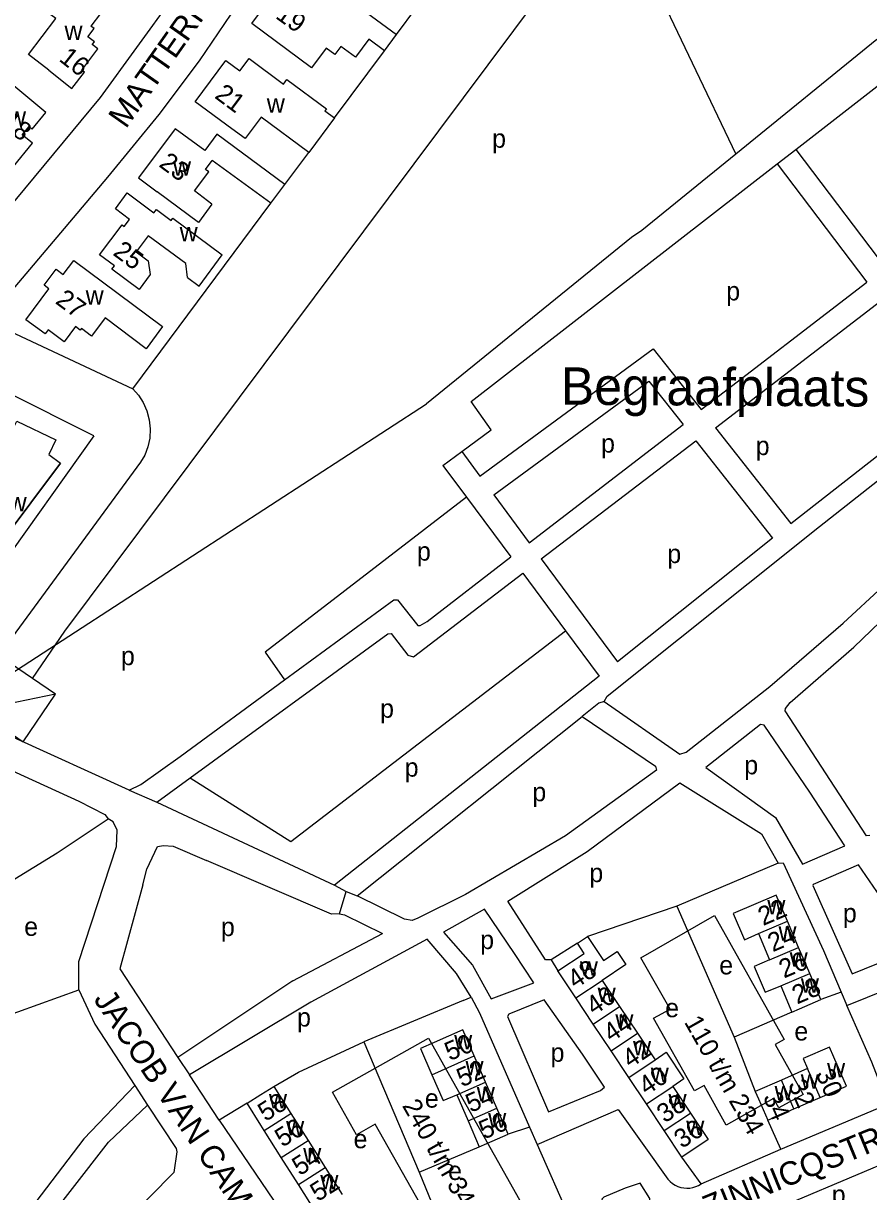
# Model space of a CAD drawing. Extents: x 158848 to 160613, y 385889 to 387762.
# Drawn here: x 159449.2 to 159630.1, y 386409.7 to 386659.8 of the extents above; entities that cross this region are included whole.
import ezdxf

# ---------------------------------------------------------------- set-up
doc = ezdxf.new("R2010")
doc.units = 0
for name, color, linetype in [('BLT_Basislijn', 7, 'Continuous'), ('BLT_Bebouwing', 7, 'Continuous'), ('BLT_Centroide', 7, 'Continuous'), ('BLT_Hoogspanningsmast_en_leidingen', 7, 'Continuous'), ('BLT_Huisnummer', 7, 'Continuous'), ('BLT_Huisnummer_ tussenligend', 7, 'Continuous'), ('BLT_Huisnummer_zonder_bebouwing', 7, 'Continuous'), ('BLT_Onderverdeling_panden', 7, 'Continuous'), ('BLT_Plantopo', 7, 'Continuous'), ('BLT_Straatnaam', 7, 'Continuous'), ('BLT_Terrein_beschrifting', 7, 'Continuous')]:
    doc.layers.add(name, color=color, linetype=linetype)

msp = doc.modelspace()

# ---------------------------------------------------------------- linework, layer by layer
at = {"layer": 'BLT_Basislijn'}
for p, q in [((159465.7, 386643.87), (159484.43, 386669.82)), ((159529, 386657.37), (159533.39, 386663.27)), ((159515.73, 386639.55), (159526.45, 386653.92)), ((159442.93, 386616.47), (159465.7, 386643.87)), ((159614.48, 386632.78), (159652.08, 386583.03)), ((159505.12, 386625.27), (159510.29, 386632.12)), ((159610.53, 386629.71), (159629.72, 386604.33)), ((159472.6, 386581.49), (159502.14, 386621.26)), ((159594.22, 386577.08), (159629.72, 386604.33)), ((159597.32, 386573.15), (159632.73, 386600.34)), ((159546.9, 386562.84), (159584, 386590.07)), ((159584, 386590.07), (159594.22, 386577.08)), ((159619.58, 386552.04), (159662.24, 386585.81)), ((159549.87, 386558.82), (159583.06, 386583.18)), ((159583.06, 386583.18), (159590.38, 386573.88)), ((159613.45, 386552.66), (159648.15, 386579.94)), ((159436.03, 386513.78), (159535.46, 386578.29)), ((159557.46, 386548.57), (159590.38, 386573.88)), ((159597.32, 386573.15), (159613.45, 386552.66)), ((159464.23, 386571.47), (159427.12, 386519.34)), ((159560.03, 386545.1), (159593.12, 386570.4)), ((159593.12, 386570.4), (159609.52, 386549.57)), ((159538.97, 386565.14), (159542.99, 386568.12)), ((159542.99, 386568.12), (159546.9, 386562.84)), ((159474.24, 386565.81), (159436.03, 386513.78)), ((159538.97, 386565.14), (159544.03, 386558.31)), ((159544.03, 386558.31), (159553.5, 386545.53)), ((159549.87, 386558.82), (159557.46, 386548.57)), ((159609.52, 386549.57), (159576.31, 386523.11)), ((159560.03, 386545.1), (159576.31, 386523.11)), ((159556.06, 386542.06), (159565.22, 386529.68)), ((159565.22, 386529.68), (159572.38, 386520.01)), ((159572.38, 386520.01), (159515.76, 386475.24)), ((159482.71, 386502.79), (159505.08, 386519.19)), ((159520.58, 386472.97), (159568.76, 386511.35)), ((159471.83, 386495.63), (159447.04, 386506.91)), ((159477.73, 386493.01), (159484.86, 386498.21)), ((159471.83, 386495.63), (159477.73, 386493.01)), ((159625.02, 386483.67), (159617.53, 386495.16)), ((159477.73, 386493.01), (159515.76, 386475.24)), ((159615.93, 386479.73), (159625.02, 386483.67)), ((159610.71, 386479.97), (159589.04, 386470.76)), ((159474.75, 386475.32), (159473.09, 386469.33)), ((159515.76, 386475.24), (159518.29, 386473.93)), ((159516.82, 386469.1), (159518.29, 386473.93)), ((159518.29, 386473.93), (159520.58, 386472.97)), ((159547.84, 386470.12), (159539.07, 386465.22)), ((159554.29, 386460.65), (159547.84, 386470.12)), ((159589.04, 386470.76), (159569.94, 386464.28)), ((159589.04, 386470.76), (159601.29, 386442.71)), ((159506.82, 386454.77), (159526.04, 386464.89)), ((159567.76, 386462.83), (159562.17, 386459.27)), ((159558.4, 386454.38), (159554.29, 386460.65)), ((159562.17, 386459.27), (159563.57, 386456.9)), ((159438.38, 386444.67), (159461.05, 386452.86)), ((159506.82, 386454.77), (159482.2, 386438.36)), ((159549.31, 386450.96), (159558.4, 386454.38)), ((159624.19, 386452.34), (159619.88, 386450.76)), ((159624.19, 386452.34), (159625.41, 386449.52)), ((159543.27, 386450.59), (159522.02, 386441.74)), ((159543.27, 386450.59), (159544.99, 386451.28)), ((159613.67, 386448.1), (159601.29, 386442.71)), ((159601.29, 386442.71), (159605.79, 386431.11)), ((159522.02, 386441.74), (159533.91, 386413.81)), ((159482.2, 386438.36), (159484.72, 386434.63)), ((159473, 386432.36), (159475.74, 386428.18)), ((159491.08, 386424.94), (159484.72, 386434.63)), ((159497.05, 386428.56), (159491.08, 386424.94)), ((159491.08, 386424.94), (159518.29, 386385)), ((159611.3, 386418.76), (159608.49, 386424.92)), ((159557.53, 386423.46), (159552.96, 386421.93)), ((159557.53, 386423.46), (159559.12, 386419.76)), ((159533.91, 386413.81), (159546.76, 386419.24)), ((159559.12, 386419.76), (159566.17, 386403.78)), ((159594.26, 386411.31), (159611.3, 386418.76)), ((159594.26, 386411.31), (159590.12, 386417.03)), ((159533.91, 386413.81), (159538.67, 386402.16))]:
    msp.add_line(p, q, dxfattribs=at)
for points in [[(159640.46, 386758.72), (159582.99, 386670.93), (159601.65, 386631.78)], [(159525.43, 386728.39), (159522.28, 386725.59), (159524.59, 386715.96), (159523.16, 386709.25), (159518.85, 386700.63), (159512.15, 386689.13), (159503.53, 386676.68), (159494.92, 386663.75), (159486.78, 386651.78), (159478.17, 386640.28), (159467.16, 386626.87), (159457.11, 386614.9), (159446.58, 386602.45), (159442.27, 386597.18), (159445.23, 386594.38), (159472.6, 386581.49)], [(159631.81, 386656.29), (159601.65, 386631.78)], [(159614.48, 386632.78), (159645.31, 386656.72), (159664.62, 386630.27), (159663.76, 386629.25), (159669.81, 386618.52), (159668.03, 386615.51), (159677.14, 386603.26), (159659.74, 386589.06)], [(159464.23, 386571.47), (159427.07, 386590.06), (159421.88, 386590.64), (159403.73, 386596.98), (159386.43, 386603.9), (159368.85, 386611.97), (159352.13, 386620.33), (159334.84, 386629.26), (159323.02, 386636.18), (159319.56, 386638.2), (159318.41, 386637.62), (159293.33, 386585.16), (159293.91, 386582.57), (159426.49, 386519.73), (159427.12, 386519.34)], [(159610.53, 386629.71), (159614.48, 386632.78)], [(159601.65, 386631.78), (159581.52, 386615.43), (159579.3, 386613.91), (159535.46, 386578.29)], [(159542.99, 386568.12), (159549.3, 386572.73), (159545.03, 386578.83), (159610.53, 386629.71)], [(159573.48, 386514.55), (159589.7, 386503.28), (159591.03, 386503.75), (159608.94, 386517.82), (159624.63, 386531.34), (159650.13, 386554.93), (159661.12, 386566.05), (159675.68, 386579.96), (159696.76, 386599.11), (159720.05, 386617.5)], [(159472.6, 386581.49), (159473.79, 386580.15), (159474.81, 386578.58), (159475.61, 386576.82), (159476.12, 386574.92), (159476.33, 386572.95), (159476.22, 386570.99), (159475.82, 386569.1), (159475.14, 386567.35), (159474.24, 386565.81)], [(159544.03, 386558.31), (159500.93, 386525.17), (159505.08, 386519.19)], [(159573.48, 386514.55), (159574.14, 386515.74), (159619.58, 386552.04)], [(159630.33, 386485.91), (159629.62, 386485.81), (159612.22, 386512.57), (159612.29, 386513.11), (159613.3, 386514.39), (159626.94, 386526.22), (159649.36, 386547.83), (159649.99, 386548.11), (159652.21, 386545.34), (159677.32, 386509.58)], [(159505.08, 386519.19), (159528.45, 386536.33), (159529.24, 386536.37), (159533.63, 386530.87), (159534.09, 386530.87), (159535.57, 386531.74), (159553.5, 386545.53)], [(159484.86, 386498.21), (159527.18, 386529.09), (159527.91, 386529.12), (159531.47, 386524.5), (159532.68, 386524.18), (159556.06, 386542.06)], [(159484.86, 386498.21), (159506.42, 386484.59), (159565.22, 386529.68)], [(159573.48, 386514.55), (159572.33, 386514.26), (159568.76, 386511.35)], [(159568.76, 386511.35), (159584.45, 386500.74), (159584.7, 386499.85), (159565.2, 386485.85), (159543.82, 386473.3), (159533.61, 386468.19), (159532.36, 386467.68), (159530.71, 386467.98), (159520.58, 386472.97)], [(159617.53, 386495.16), (159607.72, 386509.55), (159606.97, 386509.68), (159595.26, 386500.44), (159610.15, 386489.76), (159615.93, 386479.73)], [(159437.6, 386503.98), (159461.06, 386493.23), (159466.62, 386490.42), (159467.3, 386489.43)], [(159471.83, 386495.63), (159474.32, 386496.78), (159482.71, 386502.79)], [(159562.17, 386459.27), (159560.9, 386459.28), (159552.88, 386471.85), (159569.82, 386482.49), (159589.7, 386497.14), (159607.12, 386486.22), (159610.71, 386479.97)], [(159428.22, 386464.88), (159456.38, 386482.21), (159467.3, 386489.43)], [(159461.05, 386452.86), (159461.06, 386458.9), (159469.11, 386483.55), (159469.23, 386487.03), (159468.38, 386488.81), (159467.3, 386489.43)], [(159474.75, 386475.32), (159475.61, 386478.66), (159477.88, 386483.56), (159479.18, 386483.78), (159481.26, 386483.62), (159488.35, 386480.55)], [(159516.82, 386469.1), (159515.09, 386469.02), (159488.35, 386480.55)], [(159610.71, 386479.97), (159611.81, 386480.08), (159620.45, 386461.27), (159624.19, 386452.34)], [(159635.8, 386468.19), (159627.94, 386479.64), (159618.23, 386475.44), (159618.12, 386475.16), (159626.54, 386456.26), (159634.84, 386459.65), (159639.77, 386462.04), (159635.8, 386468.19)], [(159473.09, 386469.33), (159469.81, 386457.37), (159482.2, 386438.36)], [(159516.82, 386469.1), (159517.89, 386468.94), (159526.04, 386464.89)], [(159539.07, 386465.22), (159545.31, 386458.17), (159549.31, 386450.96)], [(159535.58, 386463.67), (159510.69, 386450.21), (159484.72, 386434.63)], [(159544.99, 386451.28), (159541.85, 386456.33), (159535.58, 386463.67)], [(159625.41, 386449.52), (159643.13, 386456.61), (159654.63, 386440.39), (159655.51, 386439.74), (159657.46, 386439.11), (159660.35, 386439.44), (159661.15, 386439.82)], [(159461.05, 386452.86), (159464.46, 386445.5), (159473, 386432.36)], [(159544.99, 386451.28), (159546.77, 386447.9), (159557.53, 386423.46)], [(159568.83, 386439.08), (159560.65, 386450.74), (159553.04, 386447.67), (159552.76, 386447.14), (159561.58, 386426.72), (159572.67, 386431.28), (159573.56, 386432.01), (159568.83, 386439.08)], [(159611.3, 386418.76), (159631.95, 386427.42), (159633.52, 386428.63), (159633.71, 386429.77), (159630.8, 386437.39), (159625.41, 386449.52)], [(159502.76, 386432.18), (159508.02, 386435.26), (159522.02, 386441.74)], [(159473, 386432.36), (159462.11, 386420.94), (159440.16, 386392.21), (159414.81, 386370.75), (159413.46, 386368.41), (159413.43, 386365.42), (159415.73, 386361.26), (159495.3, 386232.05)], [(159450.18, 386340.58), (159439.6, 386334.13), (159437.93, 386333.69), (159418.04, 386365.52), (159418.17, 386367.3), (159419.09, 386369.02), (159444.29, 386390.46), (159467.36, 386420.26), (159475.74, 386428.18)], [(159475.74, 386428.18), (159481.84, 386418.87), (159481.99, 386418.14), (159481.36, 386413.78), (159439.89, 386371.77), (159438.58, 386370.38), (159436.98, 386366.85), (159437.23, 386361.6), (159450.18, 386340.58)], [(159559.12, 386419.76), (159576.5, 386427.2), (159587.14, 386412.3)], [(159614.47, 386407.77), (159637.5, 386417.49), (159638.83, 386417.79), (159642.29, 386409.95)], [(159577.99, 386410.41), (159573.39, 386408.49), (159572.99, 386408.05), (159573.95, 386405.27), (159575.54, 386403.54), (159576.65, 386403.09), (159578.72, 386403.31), (159582.57, 386405.43), (159583.17, 386406.08), (159583.27, 386408.15), (159581.15, 386411.45), (159577.99, 386410.41)], [(159587.14, 386412.3), (159587.59, 386411.82), (159588.1, 386411.41), (159588.65, 386411.06), (159589.25, 386410.78), (159589.87, 386410.57), (159590.51, 386410.44), (159591.16, 386410.39), (159591.82, 386410.42), (159592.46, 386410.53), (159593.09, 386410.72), (159593.69, 386410.98), (159594.26, 386411.31)]]:
    msp.add_lwpolyline(points, dxfattribs=at)
at = {"layer": 'BLT_Bebouwing'}
for p, q in [((159615.09, 386461.95), (159612.7, 386467.54)), ((159606.49, 386464.89), (159608.88, 386459.29)), ((159567.76, 386462.83), (159569.94, 386464.28)), ((159617.48, 386456.35), (159615.09, 386461.95)), ((159567.42, 386451.12), (159563.57, 386456.9)), ((159573.06, 386454.87), (159576.79, 386449.26)), ((159619.88, 386450.76), (159617.48, 386456.35)), ((159611.28, 386453.7), (159613.67, 386448.1)), ((159571.16, 386445.51), (159567.42, 386451.12)), ((159576.79, 386449.26), (159580.58, 386443.56)), ((159574.95, 386439.81), (159571.16, 386445.51)), ((159580.58, 386443.56), (159584.38, 386437.87)), ((159548.11, 386433.11), (159545.68, 386438.69)), ((159578.74, 386434.12), (159574.95, 386439.81)), ((159616.98, 386435.98), (159611.41, 386433.55)), ((159550.54, 386427.52), (159548.11, 386433.11)), ((159582.54, 386428.42), (159578.74, 386434.12)), ((159611.41, 386433.55), (159605.79, 386431.11)), ((159502.76, 386432.18), (159506.43, 386426.39)), ((159541.91, 386430.41), (159544.34, 386424.83)), ((159588.17, 386432.17), (159591.96, 386426.47)), ((159614.11, 386427.37), (159619.72, 386429.82)), ((159552.96, 386421.93), (159550.54, 386427.52)), ((159586.33, 386422.72), (159582.54, 386428.42)), ((159608.49, 386424.92), (159614.11, 386427.37)), ((159506.43, 386426.39), (159510.09, 386420.6)), ((159544.34, 386424.83), (159546.76, 386419.24)), ((159504.38, 386416.98), (159500.71, 386422.77)), ((159590.12, 386417.03), (159586.33, 386422.72)), ((159510.09, 386420.6), (159513.75, 386414.8)), ((159508.04, 386411.19), (159504.38, 386416.98)), ((159513.75, 386414.8), (159517.42, 386409.01)), ((159511.71, 386405.4), (159508.04, 386411.19))]:
    msp.add_line(p, q, dxfattribs=at)
for points in [[(159498.05, 386659.71), (159504.39, 386668.27), (159506.05, 386667.02), (159508.68, 386670.57), (159514.67, 386666.12), (159514.4, 386665.77), (159516.11, 386664.52), (159517.29, 386666.08), (159529, 386657.37)], [(159454.6, 386649.75), (159450.25, 386653.07), (159456.15, 386660.78), (159455.07, 386661.61), (159460.16, 386668.27)], [(159460.16, 386668.27), (159465.69, 386661.9), (159463.63, 386659.18)], [(159454.6, 386649.75), (159459.54, 386645.8), (159462.23, 386649.31), (159461.67, 386649.74), (159465.14, 386654.29), (159463.92, 386655.22), (159464.39, 386655.84), (159462.99, 386656.91), (159464.32, 386658.65), (159463.63, 386659.18)], [(159526.45, 386653.92), (159523.11, 386656.41), (159520.23, 386652.54), (159517.14, 386654.85), (159515.83, 386653.09), (159513.99, 386654.46), (159510.84, 386650.23), (159498.05, 386659.71)], [(159526.45, 386653.92), (159529, 386657.37)], [(159510.29, 386632.12), (159500.07, 386639.68), (159496.61, 386635.11), (159493.81, 386637.18), (159485.96, 386642.99), (159492.5, 386651.81), (159495.49, 386649.61), (159497.48, 386652.25), (159504.84, 386646.77), (159505.57, 386647.75), (159514.04, 386641.48)], [(159437.77, 386635.89), (159445.06, 386629.88), (159445.49, 386630.39), (159447.02, 386629.13), (159451.13, 386634.13), (159448.94, 386635.92), (159450.43, 386637.7), (159451.08, 386637.15), (159453.99, 386640.72), (159446.7, 386646.73)], [(159514.04, 386641.48), (159513.71, 386641.05), (159515.73, 386639.55)], [(159515.73, 386639.55), (159510.29, 386632.12)], [(159505.12, 386625.27), (159490.58, 386636.07), (159487.98, 386632.52), (159481.63, 386637.18), (159473.82, 386626.72), (159477.82, 386623.73)], [(159489.51, 386621.07), (159485.78, 386623.9), (159488.85, 386627.97), (159488.15, 386628.5), (159489.61, 386630.43)], [(159502.14, 386621.26), (159489.61, 386630.43)], [(159502.14, 386621.26), (159505.12, 386625.27)], [(159468.12, 386607.12), (159468.66, 386607.83), (159465.49, 386610.18), (159470.29, 386616.62), (159470.76, 386616.27), (159471.9, 386617.8), (159468.86, 386620.06), (159471.39, 386623.46)], [(159471.39, 386623.46), (159477.12, 386619.19)], [(159489.51, 386621.07), (159486.63, 386617.14), (159477.82, 386623.73)], [(159477.12, 386619.19), (159477.65, 386619.9), (159480.81, 386617.56), (159481.17, 386618.04), (159491.73, 386610.18)], [(159484.32, 386605.36), (159483.92, 386608.34), (159475.88, 386614.29), (159473.32, 386610.83), (159475.87, 386608.95), (159476.29, 386605.97), (159473.94, 386602.79), (159468.12, 386607.12)], [(159486.77, 386603.54), (159491.73, 386610.18)], [(159478.98, 386594.86), (159475.48, 386590.11), (159466.64, 386596.69), (159463.76, 386592.81), (159461.6, 386594.46), (159461.32, 386594.08), (159460.31, 386594.85), (159457.9, 386591.61), (159454.48, 386594.15), (159453.8, 386593.27), (159449.72, 386596.32), (159454.61, 386602.92), (159453.59, 386603.69), (159456.19, 386607.17), (159457.72, 386605.97), (159459.98, 386608.99), (159478.98, 386594.86)], [(159484.32, 386605.36), (159486.77, 386603.54)], [(159437.43, 386572.83), (159439.55, 386577.36), (159444.27, 386575.15), (159443.81, 386574.18), (159446.87, 386572.72), (159447.77, 386574.61), (159456.14, 386570.62), (159454.62, 386567.44), (159457.08, 386565.63), (159444.41, 386548.63), (159437.96, 386551.73)], [(159444.41, 386548.63), (159457.08, 386565.63)], [(159612.7, 386467.54), (159610.3, 386473.13), (159601.09, 386469.19), (159603.51, 386463.53), (159606.49, 386464.89)], [(159563.57, 386456.9), (159569.21, 386460.66), (159567.76, 386462.83)], [(159569.94, 386464.28), (159573.36, 386459.14), (159576.26, 386461.07), (159578.13, 386458.25), (159573.06, 386454.87)], [(159608.88, 386459.29), (159605.55, 386457.86), (159607.91, 386452.34), (159611.28, 386453.7)], [(159613.67, 386448.1), (159615.28, 386448.79), (159619.88, 386450.76)], [(159545.68, 386438.69), (159543.26, 386444.28), (159537.06, 386441.59), (159534.16, 386440.33), (159536.61, 386434.67)], [(159619.72, 386429.82), (159625.34, 386432.26), (159622.64, 386438.45), (159621.71, 386440.6), (159616.05, 386438.13), (159616.98, 386435.98)], [(159584.38, 386437.87), (159586.77, 386439.49), (159590.54, 386433.83), (159588.17, 386432.17)], [(159536.61, 386434.67), (159539.01, 386429.15), (159541.91, 386430.41)], [(159497.05, 386428.56), (159500, 386430.43), (159502.76, 386432.18)], [(159605.79, 386431.11), (159606.49, 386429.5), (159608.49, 386424.92)], [(159500.71, 386422.77), (159500, 386423.9), (159497.05, 386428.56)], [(159591.96, 386426.47), (159595.75, 386420.78), (159590.12, 386417.03)], [(159546.76, 386419.24), (159548.38, 386419.94), (159552.96, 386421.93)]]:
    msp.add_lwpolyline(points, dxfattribs=at)
at = {"layer": 'BLT_Hoogspanningsmast_en_leidingen'}
for p, q in [((159458.04, 386529.66), (159564.87, 386672.58)), ((159451.11, 386519.48), (159458.04, 386529.66)), ((159456.05, 386516.12), (159439.25, 386512.66))]:
    msp.add_line(p, q, dxfattribs=at)
msp.add_lwpolyline([(159446.18, 386522.84), (159439.25, 386512.66), (159449.12, 386505.94), (159456.05, 386516.12)], close=True, dxfattribs=at)
at = {"layer": 'BLT_Onderverdeling_panden'}
for p, q in [((159606.49, 386464.89), (159612.7, 386467.54)), ((159608.88, 386459.29), (159615.09, 386461.95)), ((159567.42, 386451.12), (159573.06, 386454.87)), ((159611.28, 386453.7), (159617.48, 386456.35)), ((159571.16, 386445.51), (159576.79, 386449.26)), ((159574.95, 386439.81), (159580.58, 386443.56)), ((159536.61, 386434.67), (159545.68, 386438.69)), ((159578.74, 386434.12), (159584.38, 386437.87)), ((159619.72, 386429.82), (159616.98, 386435.98)), ((159541.91, 386430.41), (159548.11, 386433.11)), ((159614.11, 386427.37), (159611.41, 386433.55)), ((159582.54, 386428.42), (159588.17, 386432.17)), ((159544.34, 386424.83), (159550.54, 386427.52)), ((159500.71, 386422.77), (159506.43, 386426.39)), ((159586.33, 386422.72), (159591.96, 386426.47)), ((159504.38, 386416.98), (159510.09, 386420.6)), ((159508.04, 386411.19), (159513.75, 386414.8))]:
    msp.add_line(p, q, dxfattribs=at)
at = {"layer": 'BLT_Plantopo'}
for points in [[(159581.36, 386459.69), (159597.07, 386468.78), (159612.01, 386442.22), (159610.06, 386441.12), (159616.06, 386430.45), (159610.86, 386427.57), (159609.72, 386429.6), (159599.61, 386423.91), (159594.86, 386432.36), (159592.81, 386431.21), (159584.07, 386446.76), (159587.6, 386448.75)], [(159515.35, 386430.93), (159535.89, 386442.48), (159557.28, 386404.45), (159540.77, 386395.17), (159524.5, 386424.1), (159520.46, 386421.83)]]:
    msp.add_lwpolyline(points, close=True, dxfattribs=at)

# ---------------------------------------------------------------- texts
at = {"layer": 'BLT_Centroide'}
for s, p in [('w', (159457.97, 386656.23)), ('w', (159501.27, 386640.62)), ('w', (159445.88, 386637.89)), ('p', (159549.5, 386633.13)), ('w', (159481.2, 386627.16)), ('w', (159482.62, 386613.12)), ('w', (159462.5, 386599.56)), ('p', (159599.6, 386600.46)), ('p', (159572.81, 386567.87)), ('p', (159605.91, 386567.34)), ('w', (159446.02, 386555.28)), ('p', (159533.4, 386544.74)), ('p', (159586.99, 386544.22)), ('p', (159470.05, 386522.36)), ('p', (159525.52, 386511.1)), ('p', (159530.78, 386498.49)), ('p', (159603.47, 386498.99)), ('p', (159558.1, 386493.23)), ('p', (159570.3, 386475.91)), ('w', (159608.4, 386469)), ('p', (159624.57, 386467.31)), ('e', (159449.34, 386464.41)), ('p', (159491.45, 386464.36)), ('w', (159610.79, 386463.41)), ('p', (159546.94, 386461.58)), ('w', (159613.19, 386457.81)), ('w', (159568.28, 386455.92)), ('e', (159598.11, 386456.16)), ('w', (159615.58, 386452.22)), ('w', (159572.08, 386450.23)), ('e', (159586.53, 386446.99)), ('p', (159507.74, 386444.99)), ('w', (159575.88, 386444.55)), ('e', (159614.19, 386442.01)), ('w', (159541.37, 386440.12)), ('p', (159562.01, 386437.45)), ('w', (159579.66, 386438.83)), ('w', (159543.8, 386434.56)), ('w', (159583.45, 386433.14)), ('w', (159621.19, 386434.12)), ('w', (159615.56, 386431.69)), ('w', (159501.73, 386427.47)), ('e', (159535.1, 386427.63)), ('w', (159546.22, 386428.97)), ('w', (159587.25, 386427.45)), ('w', (159609.95, 386429.23)), ('w', (159548.65, 386423.38)), ('w', (159591.05, 386421.75)), ('w', (159505.41, 386421.69)), ('e', (159519.84, 386418.94)), ('w', (159509.06, 386415.89)), ('e', (159540.07, 386412.14)), ('w', (159512.73, 386410.11)), ('p', (159622.19, 386407.03))]:
    msp.add_text(s, height=4, dxfattribs=at).set_placement(p)
at = {"layer": 'BLT_Huisnummer'}
for s, rotation, p in [('19', 324.2329, (159502.93, 386661.02)), ('16', 321.8372, (159456.59, 386651.88)), ('21', 323.4166, (159489.9, 386643.94)), ('18', 320.5655, (159444.24, 386638.11)), ('23', 323.3589, (159477.98, 386629.27)), ('25', 323.3589, (159468.14, 386610.32)), ('27', 323.3821, (159455.81, 386599.96)), ('22', 23.173, (159607.48, 386466.5)), ('48', 33.6666, (159567.33, 386452.93)), ('28', 23.1595, (159614.76, 386449.7)), ('44', 33.6666, (159575, 386441.52)), ('50', 23.4779, (159540.42, 386437.57)), ('40', 33.6666, (159582.57, 386430.18)), ('30', 293.5419, (159618.69, 386434.92)), ('58', 32.3262, (159500.99, 386424.54)), ('34', 293.5401, (159607.4, 386429.94)), ('56', 23.483, (159547.75, 386420.77)), ('36', 33.6666, (159590.14, 386418.76)), ('54', 32.3293, (159508.31, 386412.94))]:
    msp.add_text(s, height=4, rotation=rotation, dxfattribs=at).set_placement(p)
at = {"layer": 'BLT_Huisnummer_ tussenligend'}
for s, rotation, p in [('24', 23.173, (159609.55, 386460.88)), ('26', 23.173, (159611.96, 386455.26)), ('46', 33.6666, (159571.31, 386447.3)), ('42', 33.6666, (159579.05, 386435.97)), ('52', 23.4779, (159543, 386431.96)), ('32', 293.5419, (159612.76, 386432.66)), ('54', 23.4779, (159544.92, 386426.49)), ('38', 33.6666, (159586.45, 386424.22)), ('56', 32.3293, (159504.62, 386419.04)), ('52', 32.3293, (159512.18, 386407.4))]:
    msp.add_text(s, height=4, rotation=rotation, dxfattribs=at).set_placement(p)
at = {"layer": 'BLT_Huisnummer_zonder_bebouwing'}
for s, p in [('110 t/m 234', (159590.51, 386445.96)), ('240 t/m 342', (159530.16, 386428.06))]:
    msp.add_text(s, height=4, rotation=299.5984, dxfattribs=at).set_placement(p)
at = {"layer": 'BLT_Straatnaam'}
for s, rotation, p in [('MATTERHORN', 54.8627, (159471.11, 386637.04)), ('JACOB VAN CAMPENWEG', 303.8166, (159464.07, 386450.81)), ('VAN ZINNICQSTRAAT', 22.2583, (159581.41, 386397.84))]:
    msp.add_text(s, height=5, rotation=rotation, dxfattribs=at).set_placement(p)
at = {"layer": 'BLT_Terrein_beschrifting'}
msp.add_text('Begraafplaats', height=8, rotation=359.6436, dxfattribs=at).set_placement((159564.2, 386578.14))

doc.saveas('drawing.dxf')
